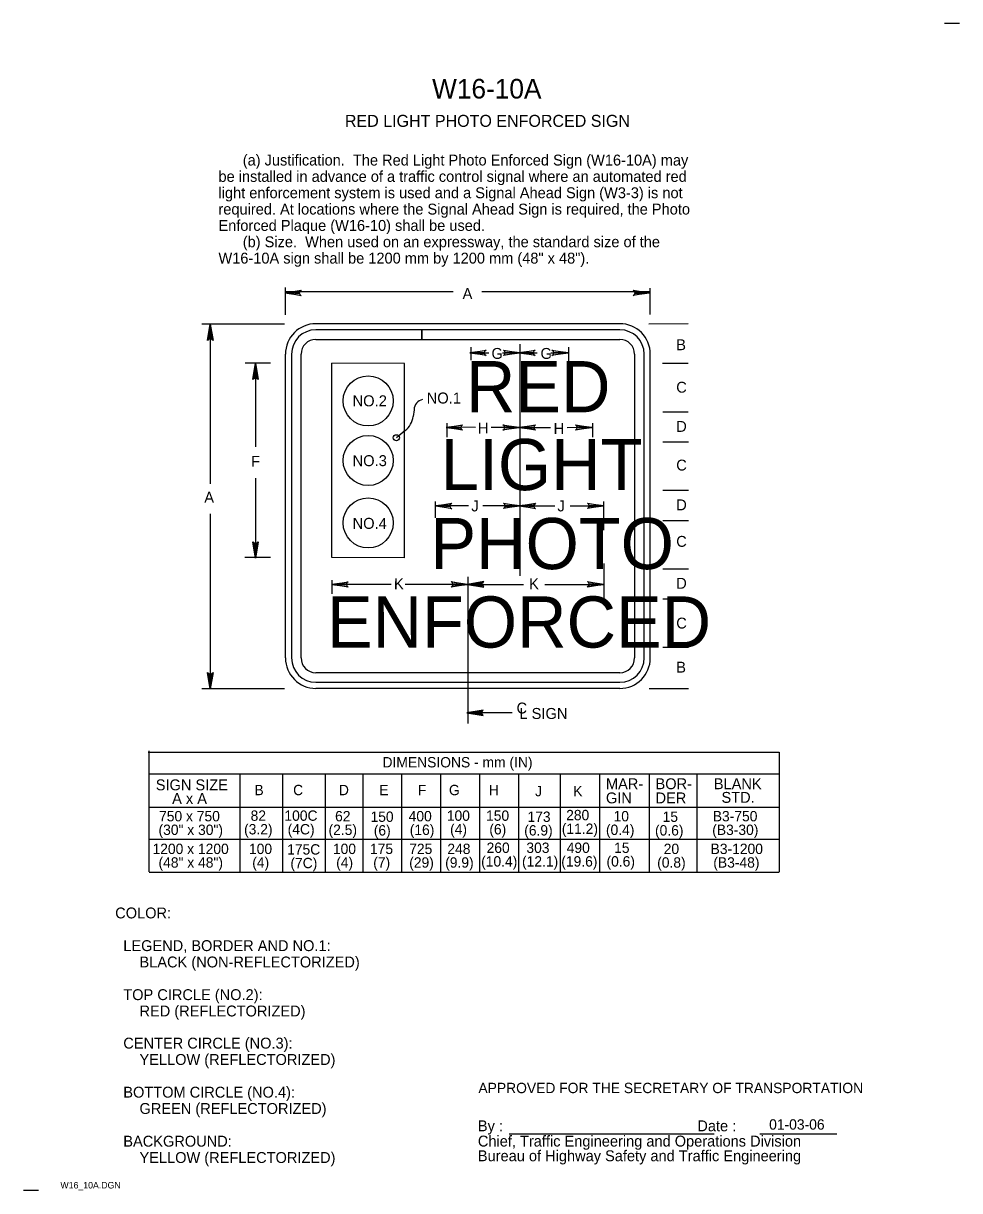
# Model space of a CAD drawing. Extents: x 0.004 to 0.219, y 0.004 to 0.272.
import ezdxf

# ---------------------------------------------------------------- set-up
doc = ezdxf.new("R2010")
doc.units = 0
for name, color, linetype in [('1', 7, 'Continuous'), ('2', 7, 'Continuous'), ('3', 7, 'Continuous'), ('4', 7, 'Continuous'), ('63', 7, 'Continuous')]:
    doc.layers.add(name, color=color, linetype=linetype)

# ---------------------------------------------------------------- blocks, each defined once
blk = doc.blocks.new('RARROW')
at = {"layer": '3'}
for p, q in [((-2.156, 0.28500000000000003), (-2.2665, 0.384625)), ((-2.2665, 0.384625), (0, 0)), ((0, 0), (-2.2665, -0.379125)), ((-2.156, 0.28500000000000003), (-2.075625, 0.12075)), ((0, 0), (-2.156, 0.28500000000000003)), ((-2.14975, -0.2705), (0, 0)), ((-2.075625, 0.12075), (0, 0)), ((0, 0), (-2.074, -0.108)), ((-2.2665, -0.379125), (-2.14975, -0.2705)), ((-2.074, -0.108), (-2.14975, -0.2705))]:
    blk.add_line(p, q, dxfattribs=at)

msp = doc.modelspace()

# ---------------------------------------------------------------- linework, layer by layer
at = {"layer": '1'}
for p, q in [((0.04503730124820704, 0.20282530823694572), (0.06398502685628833, 0.20282530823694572)), ((0.04704816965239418, 0.16608622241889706), (0.04704816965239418, 0.20282530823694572)), ((0.14092826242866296, 0.20282530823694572), (0.07122826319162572, 0.20282530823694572)), ((0.09549452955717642, 0.2014253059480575), (0.07122826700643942, 0.2014253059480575)), ((0.09549452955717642, 0.2014253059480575), (0.09549452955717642, 0.19922530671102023)), ((0.09549452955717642, 0.19922530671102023), (0.09549452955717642, 0.2014253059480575)), ((0.14092826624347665, 0.2014253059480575), (0.09549452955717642, 0.2014253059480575)), ((0.09549452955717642, 0.2014253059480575), (0.09549452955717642, 0.19922530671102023)), ((0.07122826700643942, 0.19922530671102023), (0.09549452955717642, 0.19922530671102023)), ((0.09549452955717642, 0.19922530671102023), (0.14092826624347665, 0.19922530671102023)), ((0.06422826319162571, 0.12612530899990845), (0.06422826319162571, 0.19582530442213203)), ((0.06562826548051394, 0.19582530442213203), (0.06562826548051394, 0.12612530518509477)), ((0.06782826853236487, 0.12612530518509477), (0.06782826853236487, 0.19582530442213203)), ((0.10677826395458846, 0.19745049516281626), (0.10677826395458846, 0.19444719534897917)), ((0.11797826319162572, 0.19814356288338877), (0.11797826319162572, 0.14494430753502)), ((0.12917826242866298, 0.19745049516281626), (0.12917826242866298, 0.1925990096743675)), ((0.1443282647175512, 0.19582530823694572), (0.1443282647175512, 0.12612531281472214)), ((0.14652826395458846, 0.12612531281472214), (0.14652826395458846, 0.19582530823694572)), ((0.14792826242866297, 0.12612530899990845), (0.14792826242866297, 0.19582530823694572)), ((0.057443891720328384, 0.1745746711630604), (0.057443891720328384, 0.19373450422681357)), ((0.07487826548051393, 0.14914317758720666), (0.07487826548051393, 0.19374320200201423)), ((0.09157826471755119, 0.14912596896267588), (0.09157826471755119, 0.19372598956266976)), ((0.09374831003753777, 0.18306206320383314), (0.09354059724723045, 0.1815252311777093)), ((0.10127826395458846, 0.1800103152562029), (0.10127826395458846, 0.17677599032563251)), ((0.134678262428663, 0.1800103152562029), (0.134678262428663, 0.17677599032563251)), ((0.09171866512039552, 0.17829823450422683), (0.08967580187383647, 0.176655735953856)), ((0.057443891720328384, 0.14916114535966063), (0.057443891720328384, 0.167375)), ((0.098678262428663, 0.15829414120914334), (0.098678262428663, 0.16199051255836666)), ((0.13727826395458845, 0.15545585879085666), (0.13727826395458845, 0.16199051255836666)), ((0.14792826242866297, 0.12612530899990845), (0.14792826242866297, 0.16212530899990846)), ((0.04704816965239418, 0.11912530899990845), (0.04704816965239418, 0.1592066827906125)), ((0.13727826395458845, 0.14778258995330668), (0.13727826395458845, 0.1385416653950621)), ((0.10607826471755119, 0.14470792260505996), (0.10607826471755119, 0.11109880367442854)), ((0.07487826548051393, 0.14396864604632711), (0.07487826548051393, 0.14085189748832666)), ((0.14092826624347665, 0.12272531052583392), (0.07122826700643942, 0.12272530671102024)), ((0.04503730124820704, 0.11912530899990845), (0.06398502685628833, 0.11912530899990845)), ((0.14092826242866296, 0.11912530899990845), (0.07122826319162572, 0.11912530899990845)), ((0.07122826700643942, 0.12052530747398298), (0.14092826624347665, 0.12052531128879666)), ((0.11556484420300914, 0.01694517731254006), (0.16256818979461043, 0.01694517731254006)), ((0.1730782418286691, 0.01694517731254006), (0.19068984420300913, 0.01694517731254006))]:
    msp.add_line(p, q, dxfattribs=at)
for centre, radius in [((0.08320528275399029, 0.18510747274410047), 0.005753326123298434), ((0.08320528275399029, 0.1714346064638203), 0.005753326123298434), ((0.08967580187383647, 0.176655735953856), 0.0007035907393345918), ((0.08320528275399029, 0.15711117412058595), 0.005753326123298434)]:
    msp.add_circle(centre, radius, dxfattribs=at)
for centre, radius, start, end in [((0.07122826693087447, 0.1958253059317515), 0.007, 90, 180), ((0.07122826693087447, 0.1958253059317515), 0.005599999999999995, 90, 180), ((0.14092826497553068, 0.1958253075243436), 0.007, 0, 90), ((0.14092826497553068, 0.1958253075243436), 0.005599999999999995, 0, 90), ((0.07122826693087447, 0.1958253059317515), 0.003400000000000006, 90, 180), ((0.14092826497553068, 0.1958253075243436), 0.003400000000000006, 0, 90), ((0.09622879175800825, 0.18299855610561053), 0.002481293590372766, 102.39323079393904, 178.5333926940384), ((0.08858564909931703, 0.18219492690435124), 0.005, 308.7999371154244, 352.3026989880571), ((0.07122826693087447, 0.1261253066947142), 0.007, 180, 270), ((0.07122826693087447, 0.1261253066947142), 0.005599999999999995, 180, 270), ((0.07122826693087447, 0.1261253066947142), 0.003400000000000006, 180, 270), ((0.14092826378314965, 0.12612530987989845), 0.007, 270, 0), ((0.14092826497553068, 0.1261253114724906), 0.005599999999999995, 270, 0), ((0.14092826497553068, 0.1261253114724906), 0.003400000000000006, 270, 0)]:
    msp.add_arc(centre, radius, start, end, dxfattribs=at)
at = {"layer": '3'}
for p, q in [((0.06422826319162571, 0.2048529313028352), (0.06422178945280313, 0.21113510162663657)), ((0.10274425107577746, 0.21011854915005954), (0.06422283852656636, 0.21011854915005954)), ((0.14791352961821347, 0.21011854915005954), (0.10930534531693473, 0.21011854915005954)), ((0.14791885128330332, 0.20495598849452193), (0.14791264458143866, 0.21097863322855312)), ((0.14757821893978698, 0.20282773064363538), (0.15662161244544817, 0.2028370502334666)), ((0.110875, 0.1960813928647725), (0.10677826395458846, 0.1960813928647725)), ((0.11797826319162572, 0.1960813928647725), (0.11398916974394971, 0.1960813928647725)), ((0.122, 0.1960813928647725), (0.11797826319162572, 0.1960813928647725)), ((0.12917826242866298, 0.1960813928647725), (0.12507794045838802, 0.1960813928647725)), ((0.06084850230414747, 0.19373099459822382), (0.05496687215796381, 0.1937370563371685)), ((0.09157826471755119, 0.19372598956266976), (0.07487826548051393, 0.19374320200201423)), ((0.150749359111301, 0.19373099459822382), (0.15663098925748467, 0.1937370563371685)), ((0.15076079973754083, 0.18263100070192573), (0.15664242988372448, 0.18263706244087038)), ((0.10786750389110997, 0.17903919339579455), (0.10127826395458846, 0.17904605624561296)), ((0.11797826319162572, 0.17902866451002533), (0.11139067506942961, 0.17903552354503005)), ((0.11797826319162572, 0.1790275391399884), (0.12500009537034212, 0.17903485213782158)), ((0.12888914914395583, 0.17903890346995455), (0.134678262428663, 0.17904493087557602)), ((0.15076793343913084, 0.17571100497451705), (0.1566495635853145, 0.1757170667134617)), ((0.15077937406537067, 0.16461101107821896), (0.15666100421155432, 0.16461707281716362)), ((0.10625001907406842, 0.1610183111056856), (0.098678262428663, 0.16102619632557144)), ((0.11797826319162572, 0.16100609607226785), (0.1095076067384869, 0.1610149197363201)), ((0.11797826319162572, 0.1610080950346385), (0.12599998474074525, 0.16101644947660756)), ((0.1295477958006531, 0.16102014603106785), (0.13727826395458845, 0.16102819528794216)), ((0.15078650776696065, 0.15769101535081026), (0.15666813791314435, 0.15769707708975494)), ((0.060802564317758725, 0.1491576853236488), (0.054920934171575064, 0.14916374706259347)), ((0.09157826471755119, 0.14912596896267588), (0.07487826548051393, 0.14914317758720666)), ((0.1507979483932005, 0.14659102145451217), (0.15667957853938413, 0.14659708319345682)), ((0.08849999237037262, 0.1429930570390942), (0.07487826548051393, 0.14300724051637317)), ((0.10607826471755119, 0.1429747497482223), (0.09171048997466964, 0.14298971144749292)), ((0.10607826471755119, 0.14297385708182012), (0.11887501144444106, 0.14298718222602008)), ((0.12376286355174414, 0.1429922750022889), (0.13727826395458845, 0.14300634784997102)), ((0.1508050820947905, 0.1396710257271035), (0.15668671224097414, 0.13967708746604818)), ((0.1508165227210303, 0.1285710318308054), (0.15669815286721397, 0.12857709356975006)), ((0.14766447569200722, 0.11913225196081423), (0.15670787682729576, 0.11914157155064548)), ((0.10607826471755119, 0.11357376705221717), (0.11622447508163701, 0.11358433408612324)), ((0.03275, 0.1045), (0.1775, 0.1045)), ((0.032912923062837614, 0.10482144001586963), (0.032912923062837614, 0.07700577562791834)), ((0.17750838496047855, 0.10450577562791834), (0.17750838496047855, 0.07700577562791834)), ((0.17750838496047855, 0.09943665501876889), (0.032912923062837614, 0.09943665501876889)), ((0.05375586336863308, 0.09943665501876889), (0.05375586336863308, 0.07700577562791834)), ((0.0733699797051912, 0.09943665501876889), (0.0733699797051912, 0.07700577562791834)), ((0.1476478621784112, 0.09943665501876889), (0.1476478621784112, 0.07700577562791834)), ((0.15858103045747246, 0.09943665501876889), (0.15858103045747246, 0.07700577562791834)), ((0.033, 0.091875), (0.1775, 0.091875)), ((0.17750838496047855, 0.08443876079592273), (0.032912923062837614, 0.08443876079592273)), ((0.033, 0.077), (0.1775, 0.077))]:
    msp.add_line(p, q, dxfattribs=at)
for points in [[(0.06356292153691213, 0.09943665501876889), (0.06356292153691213, 0.07700577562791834)], [(0.08196292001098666, 0.09943665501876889), (0.08196292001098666, 0.07700577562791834)], [(0.09088791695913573, 0.09943665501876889), (0.09088791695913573, 0.07700577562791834)], [(0.09981291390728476, 0.09943665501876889), (0.09981291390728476, 0.07700577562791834)], [(0.10873791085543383, 0.09943665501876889), (0.10873791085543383, 0.07700577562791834)], [(0.11766290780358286, 0.09943665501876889), (0.11766290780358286, 0.07700577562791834)], [(0.12723791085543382, 0.09943665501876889), (0.12723791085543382, 0.07700577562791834)], [(0.13626290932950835, 0.09943665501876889), (0.13626290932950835, 0.07700577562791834)]]:
    msp.add_lwpolyline(points, dxfattribs=at)
at = {"layer": '63'}
for p, q in [((0.21887500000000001, 0.27175), (0.215375, 0.27175)), ((0.007625, 0.003875), (0.004125, 0.003875))]:
    msp.add_line(p, q, dxfattribs=at)

# ---------------------------------------------------------------- block references
at = {"layer": '3'}
for p, xscale, yscale, rotation in [((0.064125, 0.209875), 0.0016545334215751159, 0.0016366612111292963, 179.91708286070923), ((0.14775, 0.209875), 0.0016545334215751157, 0.001636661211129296, -0.08291713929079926), ((0.047, 0.20275), 0.0016545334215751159, 0.0016366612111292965, 90.08291713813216), ((0.1065, 0.196125), 0.0016545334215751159, 0.0016366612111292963, 179.91708286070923), ((0.11800000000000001, 0.196125), 0.0016545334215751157, 0.001636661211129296, -0.08291713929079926), ((0.11775000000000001, 0.196125), 0.0016545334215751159, 0.0016366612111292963, 179.91708286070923), ((0.129125, 0.196125), 0.0016545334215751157, 0.001636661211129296, -0.08291713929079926), ((0.057375, 0.19375), 0.0016545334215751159, 0.0016366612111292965, 90.08291713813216), ((0.101125, 0.179), 0.0016545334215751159, 0.0016366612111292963, 179.91708286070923), ((0.11787500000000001, 0.179), 0.0016545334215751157, 0.001636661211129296, -0.08291713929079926), ((0.11787500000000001, 0.179), 0.0016545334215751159, 0.0016366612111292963, 179.91708286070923), ((0.1345, 0.179), 0.0016545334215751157, 0.001636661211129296, -0.08291713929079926), ((0.098625, 0.161), 0.001654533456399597, 0.0016530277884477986, 179.91625369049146), ((0.11800000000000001, 0.161), 0.0016545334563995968, 0.0016530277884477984, -0.08374630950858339), ((0.11787500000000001, 0.161), 0.001654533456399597, 0.0016530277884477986, 179.91625369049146), ((0.13725, 0.161), 0.0016545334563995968, 0.0016530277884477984, -0.08374630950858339), ((0.057375, 0.149), 0.0016545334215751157, 0.0016366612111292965, -89.91708286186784), ((0.074875, 0.14300000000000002), 0.001654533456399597, 0.0016530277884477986, 179.91625369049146), ((0.106, 0.14300000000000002), 0.0016545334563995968, 0.0016530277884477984, -0.08374630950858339), ((0.106, 0.14300000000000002), 0.0016545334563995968, -0.0016530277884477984, -179.91625369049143), ((0.13725, 0.14300000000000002), 0.0016545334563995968, 0.0016530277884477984, -0.08374630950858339), ((0.047, 0.11900000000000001), 0.0016545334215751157, 0.0016366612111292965, -89.91708286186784), ((0.105875, 0.1135), 0.0016545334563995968, -0.0016530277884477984, -179.91625369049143)]:
    msp.add_blockref('RARROW', p, dxfattribs=dict(at, xscale=xscale, yscale=yscale, rotation=rotation))

# ---------------------------------------------------------------- texts
at = {"layer": '1'}
for s, height, p in [('W16-10A', 0.0045000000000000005, (0.097875, 0.2545)), ('RED LIGHT PHOTO ENFORCED SIGN', 0.00275025, (0.077875, 0.248)), ('RED', 0.0117435, (0.105625, 0.1825)), ('LIGHT', 0.0117435, (0.099875, 0.164625)), ('PHOTO', 0.0117435, (0.0975, 0.1465)), ('ENFORCED', 0.0117435, (0.07375, 0.1285)), ('62', 0.0023752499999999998, (0.075625, 0.088625)), ('150', 0.0023752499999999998, (0.08375, 0.0885)), ('400', 0.0023752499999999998, (0.0925, 0.088625)), ('173', 0.0023752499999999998, (0.11975000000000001, 0.0885)), ('(2.5)', 0.0023752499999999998, (0.074125, 0.0855)), ('(6)', 0.0023752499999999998, (0.0845, 0.085375)), ('(16)', 0.0023752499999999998, (0.09275, 0.0855)), ('(6.9)', 0.0023752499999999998, (0.11900000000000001, 0.085375)), ('1200 x 1200', 0.0023752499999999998, (0.03375, 0.081125)), ('100', 0.0023752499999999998, (0.055875, 0.081125)), ('175C', 0.0023752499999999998, (0.064625, 0.081)), ('100', 0.0023752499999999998, (0.075125, 0.081125)), ('175', 0.0023752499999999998, (0.083625, 0.081125)), ('725', 0.0023752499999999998, (0.092625, 0.081125)), ('248', 0.0023752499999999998, (0.101375, 0.081125)), ('260', 0.0023752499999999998, (0.110375, 0.081375)), ('303', 0.0023752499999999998, (0.11950000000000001, 0.081375)), ('490', 0.0023752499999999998, (0.12875, 0.081375)), ('15', 0.0023752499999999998, (0.139625, 0.081375)), ('20', 0.0023752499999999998, (0.151, 0.081125)), ('B3-1200', 0.0023752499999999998, (0.16175, 0.081125)), ('(48" x 48")', 0.0023752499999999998, (0.035125, 0.078)), ('(4)', 0.0023752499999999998, (0.056625, 0.078)), ('(7C)', 0.0023752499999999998, (0.065375, 0.077875)), ('(4)', 0.0023752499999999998, (0.075875, 0.078)), ('(7)', 0.0023752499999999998, (0.084375, 0.078)), ('(29)', 0.0023752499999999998, (0.092625, 0.078)), ('(9.9)', 0.0023752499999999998, (0.100875, 0.078)), ('(10.4)', 0.0023752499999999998, (0.109125, 0.07825)), ('(12.1)', 0.0023752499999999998, (0.11850000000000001, 0.07825)), ('(19.6)', 0.0023752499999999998, (0.1275, 0.07825)), ('(0.6)', 0.0023752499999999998, (0.137875, 0.07825)), ('(0.8)', 0.0023752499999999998, (0.1495, 0.078)), ('(B3-48)', 0.0023752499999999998, (0.162375, 0.078)), ('COLOR:', 0.0024997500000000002, (0.02519168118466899, 0.06634947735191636)), ('  LEGEND, BORDER AND NO.1:', 0.0024997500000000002, (0.02519168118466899, 0.05884947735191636)), ('      BLACK (NON-REFLECTORIZED)', 0.0024997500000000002, (0.02519168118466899, 0.055099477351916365)), ('  TOP CIRCLE (NO.2):', 0.0024997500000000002, (0.02519168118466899, 0.047599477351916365)), ('      RED (REFLECTORIZED)', 0.0024997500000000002, (0.02519168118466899, 0.04384947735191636)), ('  CENTER CIRCLE (NO.3):', 0.0024997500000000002, (0.02519168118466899, 0.03647447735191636)), ('      YELLOW (REFLECTORIZED)', 0.0024997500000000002, (0.02519168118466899, 0.032724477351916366)), ('  BOTTOM CIRCLE (NO.4):', 0.0024997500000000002, (0.02519168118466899, 0.02522447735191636)), ('APPROVED FOR THE SECRETARY OF TRANSPORTATION', 0.0023752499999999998, (0.1085, 0.02625)), ('      GREEN (REFLECTORIZED)', 0.0024997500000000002, (0.02519168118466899, 0.02147447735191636)), ('By :                                                Date :', 0.0024997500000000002, (0.108375, 0.0175)), ('  BACKGROUND:', 0.0024997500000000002, (0.02519168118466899, 0.01397447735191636)), ('Chief, Traffic Engineering and Operations Division', 0.0024997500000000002, (0.108375, 0.014)), ('      YELLOW (REFLECTORIZED)', 0.0024997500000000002, (0.02519168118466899, 0.01022447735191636)), ('Bureau of Highway Safety and Traffic Engineering', 0.0024997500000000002, (0.108375, 0.010625)), ('W16_10A.DGN', 0.0015, (0.012625, 0.004375))]:
    msp.add_text(s, height=height, dxfattribs=at).set_placement(p)
at = {"layer": '2'}
for s, p in [('      (a) Justification.  The Red Light Photo Enforced Sign (W16-10A) may', (0.048875, 0.239125)), ('be installed in advance of a traffic control signal where an automated red', (0.048875, 0.235375)), ('light enforcement system is used and a Signal Ahead Sign (W3-3) is not', (0.048875, 0.231625)), ('required. At locations where the Signal Ahead Sign is required, the Photo', (0.048875, 0.227875)), ('Enforced Plaque (W16-10) shall be used.', (0.048875, 0.224125)), ('      (b) Size.  When used on an expressway, the standard size of the', (0.048875, 0.22037500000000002)), ('W16-10A sign shall be 1200 mm by 1200 mm (48" x 48").', (0.048875, 0.216625))]:
    msp.add_text(s, height=0.0024997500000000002, dxfattribs=at).set_placement(p)
at = {"layer": '3'}
for s, height, rotation, p in [('A', 0.0024997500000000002, 359.9170833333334, (0.104875, 0.2085)), ('B', 0.0024997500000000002, 359.9170833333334, (0.153875, 0.19675)), ('G', 0.0024997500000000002, 0.08291666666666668, (0.1115, 0.19475)), ('G', 0.0024997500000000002, 0.08291666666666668, (0.12275, 0.19475)), ('C', 0.0024997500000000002, 359.9170833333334, (0.153875, 0.187)), ('NO.2', 0.0025245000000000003, 359.91625555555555, (0.079625, 0.183875)), ('NO.1', 0.0025245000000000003, 0.08374444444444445, (0.096625, 0.1845)), ('H', 0.0024997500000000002, 0.08291666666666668, (0.108375, 0.177625)), ('H', 0.0024997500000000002, 0.08291666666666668, (0.12575, 0.1775)), ('D', 0.0024997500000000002, 0.08291666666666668, (0.153875, 0.178)), ('F', 0.0024997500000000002, 359.9170833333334, (0.056375, 0.17)), ('NO.3', 0.0025245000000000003, 0.08374444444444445, (0.079625, 0.170125)), ('C', 0.0024997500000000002, 0.08291666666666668, (0.153875, 0.169125)), ('A', 0.0024997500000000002, 359.9170833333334, (0.045625, 0.16175)), ('J', 0.0025245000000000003, 359.91625555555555, (0.106875, 0.15975)), ('J', 0.0025245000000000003, 0.08374444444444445, (0.12662500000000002, 0.15975)), ('D', 0.0024997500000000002, 359.9170833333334, (0.153875, 0.16)), ('NO.4', 0.0025245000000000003, 359.91625555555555, (0.079625, 0.15575)), ('C', 0.0024997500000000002, 359.9170833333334, (0.153875, 0.151625)), ('K', 0.0025245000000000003, 359.91625555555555, (0.089125, 0.141875)), ('K', 0.0025245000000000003, 0.08374444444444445, (0.120125, 0.141875)), ('D', 0.0024997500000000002, 0.08291666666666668, (0.153875, 0.14200000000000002)), ('C', 0.0024997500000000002, 359.9170833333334, (0.153875, 0.132875)), ('B', 0.0024997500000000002, 0.08291666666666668, (0.153875, 0.12275)), ('C', 0.0024997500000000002, 0.08291666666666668, (0.11725000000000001, 0.113375)), ('L SIGN', 0.0025245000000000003, 359.91625555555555, (0.11787500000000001, 0.112125))]:
    msp.add_text(s, height=height, rotation=rotation, dxfattribs=at).set_placement(p)
for s, height, p in [('DIMENSIONS - mm (IN)', 0.0023752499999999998, (0.08650000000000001, 0.101)), ('SIGN SIZE', 0.0024997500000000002, (0.0345, 0.09575)), ('B', 0.0023752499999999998, (0.057125, 0.094625)), ('C', 0.0023752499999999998, (0.066, 0.094625)), ('D', 0.0023752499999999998, (0.0765, 0.094625)), ('E', 0.0023752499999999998, (0.08575, 0.094625)), ('F', 0.0023752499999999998, (0.094625, 0.094625)), ('G', 0.0023752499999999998, (0.10175000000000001, 0.094625)), ('H', 0.0023752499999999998, (0.110875, 0.094625)), ('J', 0.0023752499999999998, (0.1215, 0.094375)), ('K', 0.0023752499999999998, (0.13025, 0.094375)), ('MAR-', 0.0024997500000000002, (0.13775, 0.096)), ('BOR-', 0.0024997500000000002, (0.149125, 0.096)), ('BLANK', 0.0024997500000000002, (0.1625, 0.096)), ('A x A', 0.0024997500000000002, (0.03825, 0.092625)), ('GIN', 0.0024997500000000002, (0.13775, 0.09275)), ('DER', 0.0024997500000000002, (0.149125, 0.09275)), ('STD.', 0.0024997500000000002, (0.16425, 0.092875)), ('82', 0.0023752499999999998, (0.05625, 0.08875)), ('100C', 0.0023752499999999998, (0.064, 0.08875)), ('100', 0.0023752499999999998, (0.10125, 0.08875)), ('150', 0.0023752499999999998, (0.11025, 0.08875)), ('280', 0.0023752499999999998, (0.128625, 0.088875)), ('750 x 750', 0.0023752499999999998, (0.035250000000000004, 0.088625)), ('10', 0.0023752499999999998, (0.1395, 0.088625)), ('15', 0.0023752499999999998, (0.15075, 0.0885)), ('B3-750', 0.0023752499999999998, (0.16225, 0.088625)), ('(30" x 30")', 0.0023752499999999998, (0.035125, 0.0855)), ('(3.2)', 0.0023752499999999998, (0.05475, 0.085625)), ('(4C)', 0.0023752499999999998, (0.06475, 0.085625)), ('(4)', 0.0023752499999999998, (0.10200000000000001, 0.085625)), ('(6)', 0.0023752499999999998, (0.111, 0.085625)), ('(11.2)', 0.0023752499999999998, (0.12762500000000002, 0.08575)), ('(0.4)', 0.0023752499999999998, (0.13775, 0.0855)), ('(0.6)', 0.0023752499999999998, (0.149, 0.085375)), ('(B3-30)', 0.0023752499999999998, (0.162125, 0.0855))]:
    msp.add_text(s, height=height, dxfattribs=at).set_placement(p)
at = {"layer": '4'}
msp.add_text('01-03-06', height=0.0023752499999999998, dxfattribs=at).set_placement((0.17518214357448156, 0.017875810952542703))

doc.saveas('drawing.dxf')
